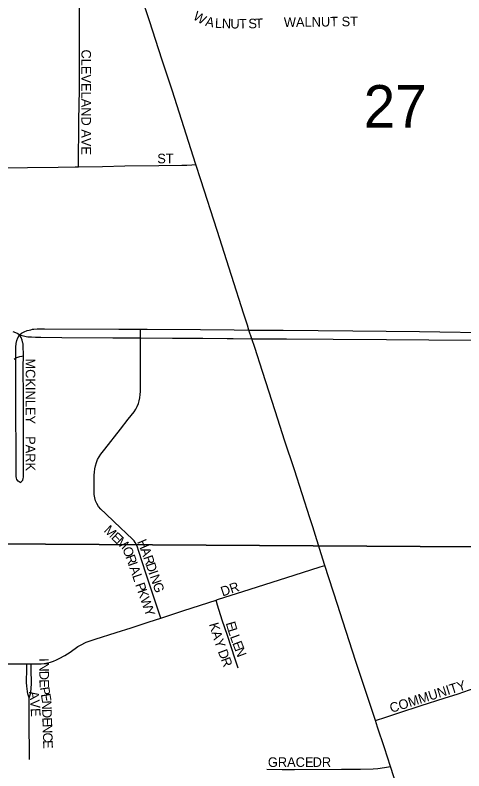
# Model space of a CAD drawing. Extents: x -97 to 34, y -21 to 22.
# Drawn here: x 5.72 to 6.163, y 18.248 to 18.994 of the extents above; entities that cross this region are included whole.
import ezdxf

# ---------------------------------------------------------------- set-up
doc = ezdxf.new("R2010")
doc.units = 0
for name, color, linetype in [('GM_X_City_Street', 7, 'Continuous'), ('GM_X_City_Street_Text', 7, 'Continuous'), ('GM_X_Section', 7, 'Continuous'), ('GM_X_Section_Text', 7, 'Continuous'), ('GM_X_State_Route', 7, 'Continuous')]:
    doc.layers.add(name, color=color, linetype=linetype)

msp = doc.modelspace()

# ---------------------------------------------------------------- linework, layer by layer
at = {"layer": 'GM_X_City_Street'}
for points in [[(5.78232, 18.84388), (5.78273, 18.89006), (5.78335, 18.91997), (5.78339, 18.93672), (5.78344, 18.9592), (5.78347, 18.98194), (5.78344, 19.0038), (5.78338, 19.01248)], [(5.78232, 18.84388), (5.80596, 18.84436), (5.82814, 18.84481), (5.86167, 18.84531), (5.88438, 18.84543), (5.88935, 18.84561), (5.89425, 18.84591), (5.89819, 18.84638)], [(5.7096, 18.84299), (5.73222, 18.84315), (5.76238, 18.84357), (5.77917, 18.84381), (5.78232, 18.84388)], [(5.71774, 18.68125), (5.72015, 18.68044), (5.72246, 18.67937), (5.72432, 18.67822)], [(5.72432, 18.67822), (5.7261, 18.67968), (5.72875, 18.68113), (5.73165, 18.68226), (5.73375, 18.68276), (5.73535, 18.6832), (5.73686, 18.68356), (5.73829, 18.68374), (5.74149, 18.68392), (5.74896, 18.6841), (5.8222, 18.68375), (5.84376, 18.68366)], [(5.84374, 18.67498), (5.84375, 18.67832), (5.84376, 18.68366)], [(5.84376, 18.68366), (5.85011, 18.68364), (5.90293, 18.68321), (5.93591, 18.68297), (5.95066, 18.68279)], [(5.95066, 18.68279), (5.96572, 18.68272), (5.98449, 18.68264), (6.01885, 18.68229), (6.05323, 18.6819), (6.11903, 18.68123), (6.19959, 18.68001), (6.25146, 18.67981)], [(5.72063, 18.65539), (5.72063, 18.65876), (5.72065, 18.6668), (5.72075, 18.66861), (5.72099, 18.6697), (5.7216, 18.67252), (5.7224, 18.67517), (5.72432, 18.67822)], [(5.72795, 18.65748), (5.7279, 18.66806), (5.72782, 18.66913), (5.72759, 18.67002), (5.7269, 18.67292), (5.72586, 18.67534), (5.72432, 18.67822)], [(5.72432, 18.67822), (5.73073, 18.67662), (5.73242, 18.67627), (5.73381, 18.67617), (5.73591, 18.67603), (5.73995, 18.67588), (5.74522, 18.67573), (5.76603, 18.67547), (5.8164, 18.67515), (5.84114, 18.67499), (5.84374, 18.67498)], [(5.8636, 18.39846), (5.86062, 18.40731), (5.85505, 18.42392), (5.84926, 18.44184), (5.8417, 18.46526), (5.84055, 18.46837), (5.83956, 18.47095), (5.83849, 18.47313), (5.83725, 18.47481), (5.83574, 18.47646), (5.81777, 18.49335), (5.80897, 18.50162), (5.80452, 18.50588), (5.80221, 18.50864), (5.80034, 18.51149), (5.79919, 18.51433), (5.79839, 18.51735), (5.79799, 18.52055), (5.79791, 18.53317), (5.79798, 18.53941), (5.79813, 18.54258), (5.79847, 18.54574), (5.79915, 18.54889), (5.80008, 18.55194), (5.80127, 18.55493), (5.80281, 18.55771), (5.80456, 18.56037), (5.80838, 18.56538), (5.82391, 18.58494), (5.83152, 18.59482), (5.83723, 18.60222), (5.83891, 18.60473), (5.84033, 18.6074), (5.84147, 18.6102), (5.84237, 18.6131), (5.84299, 18.61607), (5.84337, 18.61909), (5.84357, 18.62215), (5.8436, 18.63148), (5.84373, 18.66896), (5.84374, 18.67498)], [(5.84374, 18.67498), (5.87514, 18.67475), (5.90527, 18.67465), (5.92919, 18.67454), (5.93524, 18.67451), (5.95347, 18.67421)], [(5.95347, 18.67421), (5.95975, 18.67417), (5.98759, 18.67399), (6.03395, 18.67369), (6.08653, 18.67337), (6.17005, 18.67273), (6.21644, 18.6724), (6.25147, 18.67203)], [(5.71902, 18.65415), (5.72063, 18.65539)], [(5.72487, 18.53245), (5.72371, 18.53286), (5.72268, 18.53361), (5.72152, 18.53527), (5.72121, 18.5366), (5.72098, 18.53842), (5.72095, 18.54353), (5.72073, 18.55722), (5.72045, 18.60684), (5.72054, 18.62773), (5.72061, 18.64685), (5.72063, 18.65539)], [(5.72063, 18.65539), (5.72247, 18.6561), (5.72461, 18.65671), (5.72633, 18.6572), (5.72795, 18.65748)], [(5.72487, 18.53245), (5.7259, 18.53286), (5.72675, 18.53384), (5.72746, 18.53475), (5.72782, 18.53629), (5.72805, 18.53768), (5.72805, 18.53854), (5.72821, 18.55496), (5.72815, 18.57239), (5.72808, 18.59275), (5.72801, 18.61551), (5.72791, 18.64654), (5.72795, 18.65748)], [(5.91814, 18.41622), (5.91955, 18.41668), (5.95175, 18.42711), (5.99517, 18.44086), (6.02082, 18.44898), (6.02566, 18.45052)], [(5.8636, 18.39846), (5.88627, 18.40585), (5.91814, 18.41622)], [(5.9401, 18.34915), (5.93717, 18.35785), (5.92934, 18.38115), (5.92436, 18.39632), (5.91971, 18.4112), (5.91814, 18.41622)], [(5.73566, 18.35337), (5.74555, 18.35342), (5.74864, 18.35369), (5.75171, 18.35425), (5.75473, 18.35502), (5.75767, 18.356), (5.76055, 18.35716), (5.76337, 18.35848), (5.76885, 18.3615), (5.77411, 18.36494), (5.78178, 18.37039), (5.78448, 18.37191), (5.79004, 18.37463), (5.79893, 18.37753), (5.81974, 18.38416), (5.83455, 18.38901), (5.85226, 18.39484), (5.8636, 18.39846)], [(5.59318, 18.35152), (5.59497, 18.35238), (5.59633, 18.35276), (5.59763, 18.3528), (5.64888, 18.35306), (5.68008, 18.35303), (5.70783, 18.35325), (5.73129, 18.35335)], [(5.73371, 18.31979), (5.73253, 18.32374), (5.73213, 18.32591), (5.73169, 18.32859), (5.73139, 18.33135), (5.73119, 18.33489), (5.73127, 18.34861), (5.73129, 18.35335)], [(5.73129, 18.35335), (5.73566, 18.35337)], [(5.73371, 18.31979), (5.73499, 18.32384), (5.73548, 18.32601), (5.73577, 18.32823), (5.73596, 18.33457), (5.73576, 18.34725), (5.73566, 18.35337)], [(6.07543, 18.29742), (6.08574, 18.30072), (6.09871, 18.30487), (6.12078, 18.31224), (6.14327, 18.3194), (6.15715, 18.32376), (6.16833, 18.3276), (6.18183, 18.33187), (6.18768, 18.33362), (6.19352, 18.33496), (6.1997, 18.33529), (6.20837, 18.33529), (6.2279, 18.33513), (6.24275, 18.33496)], [(5.73412, 18.25882), (5.73362, 18.29938), (5.73371, 18.31979)], [(5.9682, 18.24929), (5.98335, 18.24895), (5.99574, 18.24912), (6.04216, 18.24947), (6.06065, 18.2495), (6.07314, 18.24957), (6.078, 18.24985), (6.08432, 18.25089), (6.09037, 18.25189)]]:
    msp.add_lwpolyline(points, dxfattribs=at)
at = {"layer": 'GM_X_Section'}
for points in [[(5.59615, 19.47364), (6.60805, 19.46219), (6.59547, 18.46625), (5.59082, 18.47236)], [(5.59082, 18.47236), (6.59547, 18.46625), (6.59419, 17.46305), (5.58508, 17.4654)]]:
    msp.add_lwpolyline(points, close=True, dxfattribs=at)
at = {"layer": 'GM_X_State_Route'}
for points in [[(5.95066, 18.68279), (5.9491, 18.68751), (5.94556, 18.69846), (5.93346, 18.73675), (5.91921, 18.78107), (5.90309, 18.83106), (5.89819, 18.84638), (5.87475, 18.9197), (5.8651, 18.94911), (5.85832, 18.96965), (5.85266, 18.98722), (5.84391, 19.01387)], [(6.01362, 18.48867), (6.01086, 18.4975), (6.00334, 18.52117), (5.99566, 18.54477), (5.98577, 18.57418), (5.97919, 18.59478), (5.9707, 18.62141), (5.96389, 18.64206), (5.95634, 18.66546), (5.95347, 18.67421), (5.95066, 18.68279)], [(6.04345, 18.39532), (6.03816, 18.41179), (6.02566, 18.45052), (6.02196, 18.46199), (6.01362, 18.48867)], [(6.11683, 18.17103), (6.11212, 18.1853), (6.10355, 18.21123), (6.09037, 18.25189), (6.08441, 18.27026), (6.07757, 18.29093), (6.07543, 18.29742), (6.05617, 18.35568), (6.04345, 18.39532)]]:
    msp.add_lwpolyline(points, dxfattribs=at)

# ---------------------------------------------------------------- texts
at = {"layer": 'GM_X_City_Street_Text'}
for s, height, rotation, p in [('W', 0.00947, 328.82865, (5.8947, 18.99015)), ('A', 0.00947, 347.35272, (5.90706, 18.9833)), ('L', 0.00947, 356.89944, (5.9169, 18.98124)), ('N', 0.00947, 358.09001, (5.92377, 18.98087)), ('U', 0.00947, 359.18199, (5.9323, 18.98058)), ('T', 0.00947, 0.57346, (5.94088, 18.98046)), ('S', 0.00947, 1.50091, (5.95021, 18.98057)), ('T', 0.00947, 1.68905, (5.95691, 18.98075)), ('WALNUT ST', 0.00947, 0.71755, (5.98519, 18.98194)), ('CLEVELAND AVE', 0.0094697, 270, (5.78527, 18.95978)), ('ST', 0.00947, 0.00001, (5.86016, 18.8474)), ('MCKINLEY', 0.00947, 270, (5.73027, 18.65478)), ('PARK', 0.00947, 270, (5.73027, 18.57811)), ('M', 0.00947, 316.26216, (5.8068, 18.4843)), ('E', 0.00947, 316.25587, (5.81402, 18.47738)), ('M', 0.00947, 316.18491, (5.81884, 18.47277)), ('H', 0.00947, 293.1326, (5.84011, 18.47387)), ('O', 0.00947, 292.28029, (5.82547, 18.46671)), ('A', 0.00947, 289.94203, (5.84333, 18.46634)), ('R', 0.00947, 289.94784, (5.82859, 18.45909)), ('R', 0.00947, 289.10321, (5.84616, 18.45854)), ('I', 0.00947, 289.29211, (5.83114, 18.45207)), ('D', 0.00947, 289.10406, (5.84861, 18.45145)), ('A', 0.00947, 289.10541, (5.83252, 18.44814)), ('L', 0.00947, 289.11662, (5.83525, 18.44027)), ('I', 0.00947, 289.09827, (5.85134, 18.44358)), ('N', 0.00947, 289.08476, (5.8527, 18.43964)), ('P', 0.00947, 289.09238, (5.83825, 18.4316)), ('K', 0.00947, 289.08476, (5.84043, 18.42531)), ('G', 0.00947, 289.10406, (5.85543, 18.43176)), ('DR', 0.00947, 18.43495, (5.9246, 18.41981)), ('W', 0.00947, 289.09871, (5.84315, 18.41743)), ('Y', 0.00947, 289.10541, (5.8467, 18.40719)), ('K', 0.00947, 285.75927, (5.91118, 18.39255)), ('E', 0.00947, 286.05801, (5.92767, 18.39359)), ('A', 0.00947, 287.54403, (5.91354, 18.38423)), ('L', 0.00947, 287.55678, (5.9296, 18.38693)), ('Y', 0.00947, 289.13963, (5.91614, 18.37601)), ('L', 0.00947, 290.28809, (5.93176, 18.38011)), ('E', 0.00947, 290.77753, (5.9341, 18.37378)), ('D', 0.00947, 290.40855, (5.91981, 18.36557)), ('N', 0.00947, 290.7786, (5.93647, 18.36754)), ('I', 0.00947, 270.69923, (5.74361, 18.35891)), ('N', 0.00947, 270.67764, (5.74366, 18.35475)), ('R', 0.00947, 290.54778, (5.92272, 18.35774)), ('D', 0.00947, 270.69119, (5.74376, 18.34641)), ('E', 0.00947, 270.68304, (5.74386, 18.33808)), ('COMMUNITY', 0.00947, 17.6235, (6.09127, 18.30481)), ('A', 0.00947, 278.99877, (5.73341, 18.32566)), ('P', 0.00947, 279.43041, (5.74408, 18.32984)), ('E', 0.00947, 279.33205, (5.74517, 18.32327)), ('V', 0.00947, 273.71813, (5.73468, 18.31765)), ('N', 0.00947, 271.7708, (5.74622, 18.31702)), ('E', 0.00947, 272.35068, (5.73522, 18.3094)), ('D', 0.00947, 271.74896, (5.74648, 18.30869)), ('E', 0.00947, 271.74896, (5.74673, 18.30036)), ('N', 0.00947, 271.76215, (5.74693, 18.2937)), ('C', 0.00947, 271.74896, (5.74719, 18.28537)), ('E', 0.00947, 271.76405, (5.74742, 18.27787)), ('GRACE', 0.00947, 0.00001, (5.96933, 18.25156)), ('DR', 0.00947, 0.00001, (6.01349, 18.25156))]:
    msp.add_text(s, height=height, rotation=rotation, dxfattribs=at).set_placement(p)
at = {"layer": 'GM_X_Section_Text'}
msp.add_text('27', height=0.041856, rotation=0.00001, dxfattribs=at).set_placement((6.06391, 18.88276))

doc.saveas('drawing.dxf')
